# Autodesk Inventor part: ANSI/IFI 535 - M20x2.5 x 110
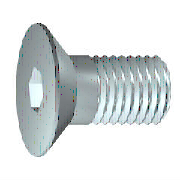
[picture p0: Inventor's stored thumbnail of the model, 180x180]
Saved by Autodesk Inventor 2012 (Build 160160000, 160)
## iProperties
Created: 2011-02
Part Number: ANSI/IFI 535 - M20x2.5 x 110
Material: Steel, Mild
Description: Broached Socket Head Cap Screw
Document SubType Name: Modeling
Standard: ANSI/IFI 535
Designer: jrr70267
Standards Organization: ANSI
Language: en-US
Size Designation: M20x2.5 x 110
Categories: <MemberInstance><Categories><Category DisplayName="Fasteners" InternalName="e4da775c-781d-43d5-af7c-5136215cf5a6" Mnemonic="FSTN"><Category DisplayName="Bolts"
Density: 1 g/cm^3
IsCustomPart: 0
Author: jrr70267
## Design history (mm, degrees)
workplane "Work Plane1"
revolve "Body" stored, may be unused: angle "d13" = 90 deg
sketch "Sketch2"
  geometry: L1 (0, -24.22)-(0, 24.22) reference; L2 (-24.22, 0)-(24.22, 0) reference; L3 (6.928, 0)-(3.464, -6); L4 (3.464, -6)-(-3.464, -6); L5 (-3.464, -6)-(-6.928, 0); L6 (-6.928, 0)-(-3.464, 6); L7 (-3.464, 6)-(3.464, 6); L8 (3.464, 6)-(6.928, 0); A1 r 6.928 centre (0, 0) between (0, 6.928) and (6.928, 0) reference; 2 further points
  constraints: 12 end point, 2 coincident, 2 point on circle, 2 point on line, 12 other
extrude "Slot" join sketch "Sketch2" taper "d14" = 0 deg; stored distance "d30" = 10
body "Solid1"
feature "Thread" dims "d15" = 52 (= GEL), "d16" = 0
chamfer "Chamfer1" distance "d17" = 2.04483 (= -0.5 x SPD + 0.5 x GD); stored, may be unused: second distance "d18" = 1.53363 (= GUL), angle "d39" = 45 deg
sketch "Sketch1"
  geometry: L1 (110, 0)-(110, 10); L2 (110, 10)-(58, 10); L3 (58, 10)-(56.466, 10); L4 (0, 17.3)-(0, 6.928); L5 (0, 6.928)-(5.6, 6.928); L6 (5.6, 6.928)-(9.6, 0); L7 (9.6, 0)-(110, 0); L8 (0, 17.3)-(2.86, 17.3); L9 (2.86, 17.3)-(10.16, 10); L10 (56.466, 10)-(10.16, 10); L11 (58, 10)-(10.16, 10); L12 (10.16, 10)-(10.16, 10); L13 (-22, 0)-(132, 0) reference; L14 (0, -3.46)-(0, 20.76) reference
  constraints: 24 end point, 4 collinear, 3 parallel
  dimensions: "d0" = 110 distance between parallel lines of L4 L1 (= NLG); "d1" = 52 distance from line of L2.end L1 (= GEL); "d2" = 5.6 distance from line of L5.end L4 (= INTI); "d3" = 20 diameter of L2 L7 (= GD); "d6" = 10.16 distance from line of L9.end L4 (= KOH); "d7" = 45 deg angle of L9 L7 (= 0.5 x SEWI); "d8" = 13.85641 diameter of L5 L7 (= 1.1547 x SW); "d9" = 60 deg angle of L6 L7; "d10" = 34.6 diameter of L8 L7 (= KOD); "d11" = 20 diameter of L10 L7 (= BDM); "d12" = 1.53363 distance of L3.end L2.end (= GAL)
other parameters: "NLG" = 110 [user parameter; used in 1 equation term], "INTI" = 5.6 [user parameter; used in 1 equation term], "GEL" = 52 [user parameter; used in 2 equation terms], "GAL" = 1.53363 (= 0.61345 x PTC) [user parameter; used in 1 equation term], "KOH" = 10.16 [user parameter; used in 1 equation term], "KOD" = 34.6 [user parameter; used in 1 equation term], "GUL" = 1.53363 (= 0.61345 x PTC) [user parameter; used in 1 equation term], "SPD" = 15.91033 [user parameter; used in 1 equation term], "BDM" = 20 (= NND) [user parameter; used in 1 equation term], "GD" = 20 (= NND) [user parameter; used in 2 equation terms], "SEWI" = 90 deg [user parameter; used in 1 equation term], "d20" = 0, "SW" = 12 [user parameter; used in 2 equation terms], "d43" = 0, "d44" = 0, "TOA" = 30 deg [user parameter], "GD1" = 16.93275 (= THREADDIA - 1.2269 x PTC) [user parameter], "EPV" = 17.3 [user parameter], "TPU" = 4 (computed from PTC) [user parameter], "PTC" = 2.5 [user parameter; used in 4 equation terms], "E0" = 13.86 (= 1.155 x SW) [user parameter]
